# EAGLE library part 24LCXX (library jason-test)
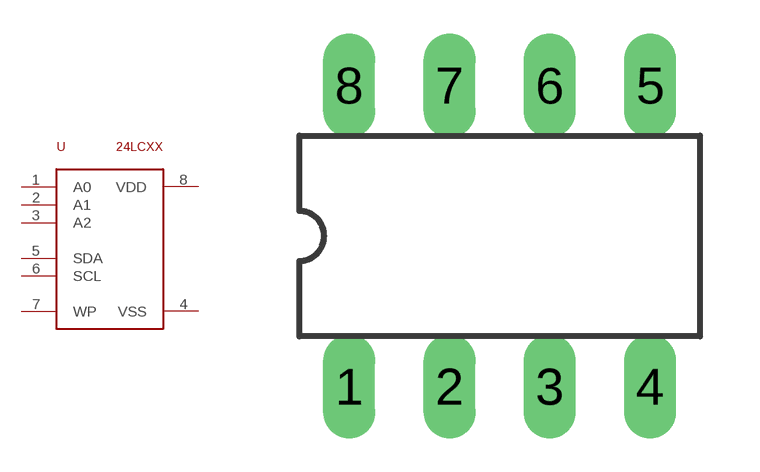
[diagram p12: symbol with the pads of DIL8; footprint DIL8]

Designator prefix -

## 24LCXXDIL  [DIL8]
1  A0  in
2  A1  in
3  A2  in
4  VSS  pwr
5  SDA
6  SCL  in
7  WP  in
8  VDD  pwr

## Footprint DIL8 (pad centres in mm)
Dual In Line package type P
drill 0.813 long: 1 -3.81,-3.81; 2 -1.27,-3.81; 3 1.27,-3.81; 4 3.81,-3.81; 5 3.81,3.81; 6 1.27,3.81; 7 -1.27,3.81; 8 -3.81,3.81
